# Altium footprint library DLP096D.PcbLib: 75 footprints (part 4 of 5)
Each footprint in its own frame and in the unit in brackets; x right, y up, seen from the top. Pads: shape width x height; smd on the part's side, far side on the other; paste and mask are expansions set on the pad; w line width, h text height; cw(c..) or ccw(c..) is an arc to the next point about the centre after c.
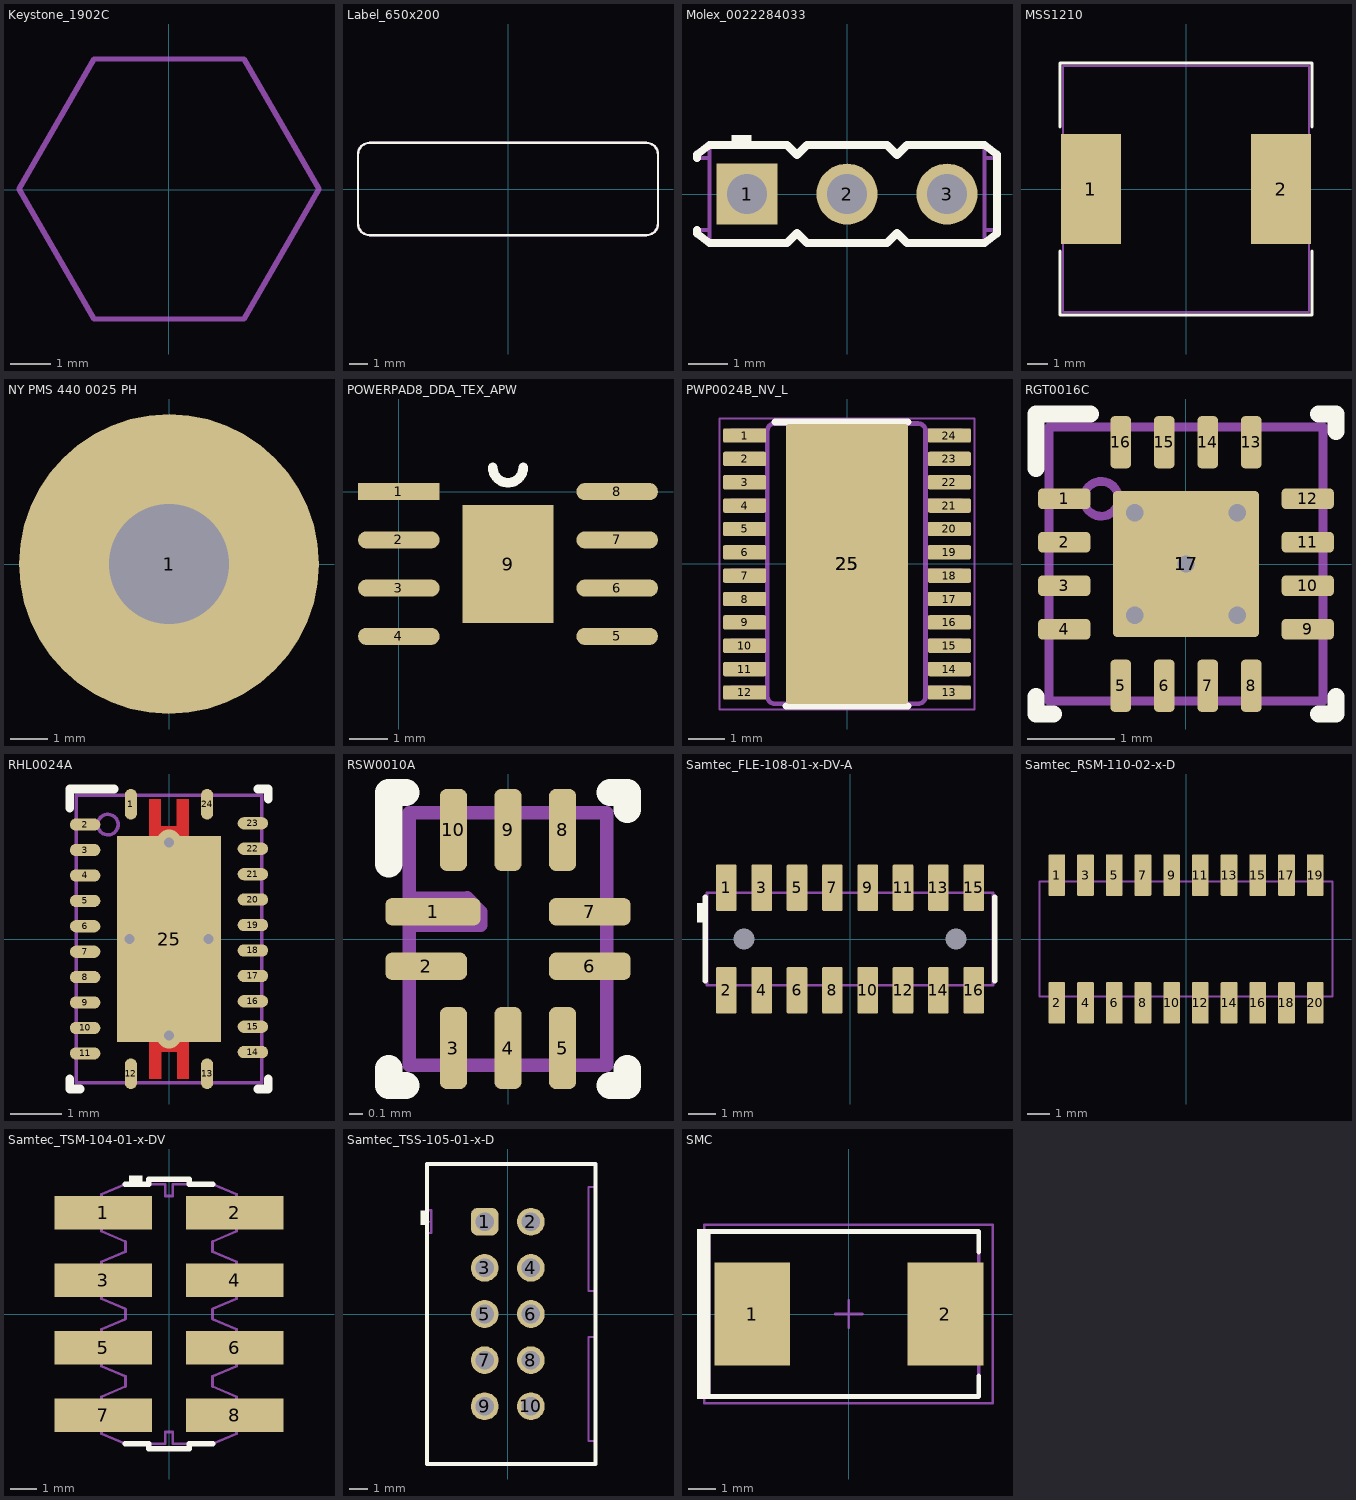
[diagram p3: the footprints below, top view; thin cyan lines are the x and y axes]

## Keystone_1902C [mil] "Hex Standoff, 4-40 threaded, nylon"
height 500
pads (1):
  round 1 on Mech3: 0(0,0)
Mechanical 5:
  lines w5: -145.29,0.49 -72.56,-125.49 72.92,-125.49 145.65,0.49 72.92,126.47 -72.56,126.47 -145.29,0.49
  text ".Designator" at -60,-20 h40
3D body "Keystone_1902C.stp": height 501, standoff 1, extent -144.95,-125.98 146,125.98

## Label_650x200 [mil] "Thermal Transfer Label"
height 1
pads (1):
  round 1 on Mech13: 0(0,0)
Top Overlay:
  lines w5: -325,-75 ccw(c-300,-75) -300,-100 300,-100 ccw(c300,-75) 325,-75 325,75 ccw(c300,75) 300,100 -300,100 ccw(c-300,75) -325,75 -325,-75
Mechanical 5:
  lines w5: -325,-75 ccw(c-300,-75) -300,-100 300,-100 ccw(c300,-75) 325,-75 325,75 ccw(c300,75) 300,100 -300,100 ccw(c-300,75) -325,75 -325,-75
  text ".Designator" at -60,-20 h40
3D body: height 1, standoff 0, extent -325.02,-100.02 325.02,100.02

## Molex_0022284033 [mm] "Header, 2.54mm, 3x1, TH"
height 8.88
pads (3):
  rect 1.55x1.55 hole 1.02: 1(-2.54,0)
  round 1.55 hole 1.02: 2(0,0) 3(2.54,0)
Top Overlay:
  rectangle: -2.93,1.245 -2.43,1.5
  lines w0.2: -3.81,-0.914 -3.81,-1.003 -3.492,-1.245 -1.524,-1.245 -1.27,-0.991 -1.016,-1.245 1.016,-1.245 1.27,-0.991 1.524,-1.245 3.492,-1.245 3.81,-1.003 3.81,-0.914 3.81,0.914 3.81,1.003 3.492,1.245 1.524,1.245 1.27,0.991 1.016,1.245 -1.016,1.245 -1.27,0.991 -1.524,1.245 -3.492,1.245 -3.81,1.003 -3.81,0.914
Mechanical 5:
  lines w0.1: -3.492,-1.168 -3.492,1.168 ; -3.492,-0.914 -3.81,-0.914 -3.81,-1.003 -3.492,-1.245 -1.524,-1.245 -1.27,-0.991 -1.016,-1.245 1.016,-1.245 1.27,-0.991 1.524,-1.245 3.492,-1.245 3.81,-1.003 3.81,-0.914 ; -3.492,0.914 -3.81,0.914 -3.81,1.003 -3.492,1.245 -1.524,1.245 -1.27,0.991 -1.016,1.245 1.016,1.245 1.27,0.991 1.524,1.245 3.492,1.245 3.81,1.003 3.81,0.914 ; 3.492,-1.168 3.492,1.168 ; 3.492,-0.914 3.81,-0.914 ; 3.492,0.914 3.81,0.914 ; 3.81,-0.914 3.81,0.914
  text ".Designator" at -2,-0.7 h1.85
3D body "022284033.stp": height 8.4, standoff -3.16, extent -3.81,-1.244 3.81,1.245

## MSS1210 [mm] "Coilcraft MSS1210 series"
height 10.2
pads (2):
  rect 3x5.5 smd: 1(-4.75,0) 2(4.75,0)
Top Overlay:
  lines w0.17: -6.3,-3.1 -6.3,-6.3 6.3,-6.3 6.3,-3.1 ; -6.3,3.1 -6.3,6.3 6.3,6.3 6.3,3.1
Mechanical 5:
  lines w0.1: -6.15,-6.15 6.15,-6.15 6.15,6.15 -6.15,6.15 -6.15,-6.15
  text ".Designator" at -2,-0.5 h1.02
3D body: height 10.2, standoff 0, extent -6.149,-6.149 6.149,6.149

## NY PMS 440 0025 PH [mm] "4-40 nylon screw and mounting hole"
height 1.905
pads (1):
  round 8 hole 3.2: 1(0,0)
Mechanical 5:
  circle w0.127: c0,0 r3.789
  text ".Designator" at -1.524,-0.508 h1.02
3D body "B_F_NY PMS 440 0025 PH.stp": height 2.69, standoff -8.74, extent -3.302,-3.3 3.296,3.3

## PCBComponent_1 [mm]

## POWERPAD8_DDA_TEX_APW [mm]
pads (9):
  rect 2.15x0.45 smd: 1(0,0)
  oval 2.15x0.45 smd: 2(0,-1.27) 3(0,-2.54) 4(0,-3.81) 5(5.75,-3.81) 6(5.75,-2.54) 7(5.75,-1.27) 8(5.75,0)
  rect 2.4x3.1 smd: 9(2.875,-1.905)
Top Overlay:
  lines w0.254: 2.475,0.635 ccw(c2.875,0.635) 3.275,0.635

## PWP0024B_NV_L [mm] "TSOP, 24-Leads, Body 7.9x4.5mm (max), Pitch 0.65mm, IPC High Density"
height 1.2
pads (27):
  rrect25% 1.2x0.4 smd: 1(-2.85,3.575) 2(-2.85,2.925) 3(-2.85,2.275) 4(-2.85,1.625) 5(-2.85,0.975) 6(-2.85,0.325) 7(-2.85,-0.325) 8(-2.85,-0.975) 9(-2.85,-1.625) 10(-2.85,-2.275) 11(-2.85,-2.925) 12(-2.85,-3.575) 13(2.85,-3.575) 14(2.85,-2.925) 15(2.85,-2.275) 16(2.85,-1.625) 17(2.85,-0.975) 18(2.85,-0.325) 19(2.85,0.325) 20(2.85,0.975) 21(2.85,1.625) 22(2.85,2.275) 23(2.85,2.925) 24(2.85,3.575)
  rrect6% 3.4x7.8 smd paste-2 mask-2: 25(0,0)
  rrect50% 2.4x5.16 on Top Paste: 25(0,0)
  rrect50% 2.4x5.16 on Top Solder: 25(0,0)
Top Overlay:
  lines w0.2: -2,3.95 1.7,3.95 ; -1.7,-3.95 1.7,-3.95
Mechanical 5:
  drawing of 298 lines, arcs and shapes, not listed
  text ".Designator" at -1.854,-0.508 h1.02
Mechanical 15:
  lines w0.05: -3.55,-4.05 3.55,-4.05 3.55,4.05 -3.55,4.05 -3.55,-4.05
  lines w0.1: -0.5,0 0.5,0 ; 0,-0.5 0,0.5
3D body "PWP0024B.stp": height 1.2, standoff 0, extent -3.208,-3.9 3.208,3.9

## RGT0016C [mm] "QFN, 16-Leads, Body 3x3mm, Pitch 0.5mm, Thermal Pad 1.7x1.7mm, TI Recommended"
height 1
pads (18):
  rrect42% 0.6x0.24 smd: 1(-1.4,0.75) 2(-1.4,0.25) 3(-1.4,-0.25) 4(-1.4,-0.75) 9(1.4,-0.75) 10(1.4,-0.25) 11(1.4,0.25) 12(1.4,0.75)
  rrect42% 0.24x0.6 smd: 5(-0.75,-1.4) 6(-0.25,-1.4) 7(0.25,-1.4) 8(0.75,-1.4) 13(0.75,1.4) 14(0.25,1.4) 15(-0.25,1.4) 16(-0.75,1.4)
  rrect50% 1.55x1.55 on Top Paste: 17(0,0)
  rrect6% 1.68x1.68 smd paste-0.85: 17(0,0)
via 0,0 diameter 0.5 hole 0.2
via -0.59,0.59 diameter 0.5 hole 0.2
via -0.59,-0.59 diameter 0.5 hole 0.2
via 0.59,-0.59 diameter 0.5 hole 0.2
via 0.59,0.59 diameter 0.5 hole 0.2
Top Overlay:
  lines w0.2: -1.725,-1.525 -1.725,-1.725 -1.525,-1.725 ; -1.725,1.1 -1.725,1.725 -1.1,1.725 ; 1.525,-1.725 1.725,-1.725 1.725,-1.525 ; 1.525,1.725 1.725,1.725 1.725,1.525
Mechanical 5:
  circle w0.1: c-0.975,0.75 r0.2
  lines w0.1: -1.575,-1.575 -1.575,1.575 1.575,1.575 1.575,-1.575 -1.575,-1.575
  text ".Designator" at -1.425,-0.55 h1.4
3D body "RGT0016C.stp": height 1, standoff 0, extent -1.5,-1.5 1.5,1.5

## RHL0024A [mm]
height 1
pads (25):
  oval 0.24x0.6 smd: 1(-0.75,2.65) 12(-0.75,-2.65) 13(0.75,-2.65) 24(0.75,2.65)
  oval 0.6x0.24 smd: 2(-1.65,2.25) 3(-1.65,1.75) 4(-1.65,1.25) 5(-1.65,0.75) 6(-1.65,0.25) 7(-1.65,-0.25) 8(-1.65,-0.75) 9(-1.65,-1.25) 10(-1.65,-1.75) 11(-1.65,-2.25) 14(1.65,-2.225) 15(1.65,-1.725) 16(1.65,-1.225) 17(1.65,-0.725) 18(1.65,-0.225) 19(1.65,0.275) 20(1.65,0.775) 21(1.65,1.275) 22(1.65,1.775) 23(1.65,2.275)
  rect 2.05x4.05 smd paste-1.1: 25(0,0)
via 0,-1.9 diameter 0.5 hole 0.2
via 0,1.9 diameter 0.5 hole 0.2
via 0.775,0 diameter 0.5 hole 0.2
via -0.775,0 diameter 0.5 hole 0.2
Top Layer:
  region: 0.396,-2 0.154,-2 0.154,-2.75 0.396,-2.75
  region: -0.152,-2 -0.394,-2 -0.394,-2.75 -0.152,-2.75
  rectangle: -0.395,2.024 0.395,2.225
  rectangle: 0.152,2 0.394,2.75
  rectangle: -0.396,2 -0.154,2.75
  rectangle: -0.395,-2.225 0.395,-2.024
Top Overlay:
  lines w0.17: -1.95,-2.75 -1.95,-2.95 -1.75,-2.95 ; -1.95,2.575 -1.95,2.95 -1.075,2.95 ; 1.75,-2.95 1.95,-2.95 1.95,-2.75 ; 1.75,2.95 1.95,2.95 1.95,2.75
Top Paste:
  rectangle: -0.895,0.1 0.894,1.798
  rectangle: -0.895,-1.798 0.894,-0.1
Mechanical 5:
  circle w0.07: c-1.202,2.25 r0.202
  lines w0.07: -1.825,-2.825 1.825,-2.825 1.825,2.825 -1.825,2.825 -1.825,-2.825
  text ".Designator" at -1.65,-0.475 h0.9
3D body: height 1, standoff 0, extent -1.824,-2.824 1.824,2.824
3D body: height 1.01, standoff 0.9, extent -1.403,2.049 -1.001,2.451

## RSW0010A [mm] "QFN, 10-Leads, Body 1.8x1.4 mm, Pitch 0.4mm, TI Recommended"
height 0.55
pads (10):
  rrect50% 0.7x0.2 smd: 1(-0.55,0.2)
  rrect50% 0.6x0.2 smd: 2(-0.6,-0.2) 6(0.6,-0.2) 7(0.6,0.2)
  rrect50% 0.2x0.6 smd: 3(-0.4,-0.8) 4(0,-0.8) 5(0.4,-0.8) 8(0.4,0.8) 9(0,0.8) 10(-0.4,0.8)
Top Overlay:
  lines w0.2: -0.875,-0.95 -0.875,-1.075 -0.75,-1.075 ; -0.875,0.55 -0.875,1.075 -0.75,1.075 ; 0.75,-1.075 0.875,-1.075 0.875,-0.95 ; 0.75,1.075 0.875,1.075 0.875,0.95
Mechanical 5:
  lines w0.1: -0.725,0.1 -0.2,0.1 -0.2,0.2 -0.3,0.3 -0.725,0.3 ; -0.725,-0.925 0.725,-0.925 0.725,0.925 -0.725,0.925 -0.725,-0.925
  text ".Designator" at 0.125,0.725 h0.38
3D body "RSW0010A.stp": height 0.56, standoff 0.01, extent -0.7,-0.9 0.7,0.9

## Samtec_FLE-108-01-x-DV-A [mm] "Receptacle, 1.27mm, 8x2, SMT"
height 4.68
pads (18):
  rrect14% 0.74x1.675 smd: 1(-4.445,1.843) 2(-4.445,-1.842) 3(-3.175,1.843) 4(-3.175,-1.842) 5(-1.905,1.843) 6(-1.905,-1.842) 7(-0.635,1.843) 8(-0.635,-1.842) 9(0.635,1.843) 10(0.635,-1.842) 11(1.905,1.843) 12(1.905,-1.842) 13(3.175,1.843) 14(3.175,-1.842) 15(4.445,1.843) 16(4.445,-1.842)
  round 0.46 hole 0.76 unplated: ""(-3.81,0) ""(3.81,0)
Top Overlay:
  rectangle: -5.5,0.6 -5.2,1.3
  lines w0.2: -5.2,-1.5 -5.2,1.5 ; 5.2,-1.5 5.2,1.5
Mechanical 5:
  lines w0.1: -4.699,-1.664 -4.699,-2.297 -4.191,-2.297 -4.191,-1.664 ; -4.699,1.664 -4.699,2.297 -4.191,2.297 -4.191,1.664 ; -3.429,-1.664 -3.429,-2.297 -2.921,-2.297 -2.921,-1.664 ; -3.429,1.664 -3.429,2.297 -2.921,2.297 -2.921,1.664 ; -2.159,-1.664 -2.159,-2.297 -1.651,-2.297 -1.651,-1.664 ; -2.159,1.664 -2.159,2.297 -1.651,2.297 -1.651,1.664 ; -0.889,-1.664 -0.889,-2.297 -0.381,-2.297 -0.381,-1.664 ; -0.889,1.664 -0.889,2.297 -0.381,2.297 -0.381,1.664 ; 0.381,-1.664 0.381,-2.297 0.889,-2.297 0.889,-1.664 ; 0.381,1.664 0.381,2.297 0.889,2.297 0.889,1.664 ; 1.651,-1.664 1.651,-2.297 2.159,-2.297 2.159,-1.664 ; 1.651,1.664 1.651,2.297 2.159,2.297 2.159,1.664 ; 2.921,-1.664 2.921,-2.297 3.429,-2.297 3.429,-1.664 ; 2.921,1.664 2.921,2.297 3.429,2.297 3.429,1.664 ; 4.191,-1.664 4.191,-2.297 4.699,-2.297 4.699,-1.664 ; 4.191,1.664 4.191,2.297 4.699,2.297 4.699,1.664 ; -5.137,-1.664 5.137,-1.664 5.137,1.664 -5.137,1.664 -5.137,-1.664
  text ".Designator" at -2.6,-0.4 h1.52
3D body "FLE-108-01-G-DV-A.stp": height 4.55, standoff -0.58, extent -5.137,-2.297 5.137,2.298

## Samtec_RSM-110-02-x-D [mm] "Receptacle, 1.27mm, 10x2, SMT"
height 6.354
pads (20):
  rrect14% 0.74x1.84 smd: 1(-5.715,2.825) 2(-5.715,-2.825) 3(-4.445,2.825) 4(-4.445,-2.825) 5(-3.175,2.825) 6(-3.175,-2.825) 7(-1.905,2.825) 8(-1.905,-2.825) 9(-0.635,2.825) 10(-0.635,-2.825) 11(0.635,2.825) 12(0.635,-2.825) 13(1.905,2.825) 14(1.905,-2.825) 15(3.175,2.825) 16(3.175,-2.825) 17(4.445,2.825) 18(4.445,-2.825) 19(5.715,2.825) 20(5.715,-2.825)
Mechanical 5:
  lines w0.1: -5.918,-2.54 -5.918,-3.238 -5.512,-3.238 -5.512,-2.54 ; -5.918,2.54 -5.918,3.238 -5.512,3.238 -5.512,2.54 ; -4.648,-2.54 -4.648,-3.238 -4.242,-3.238 -4.242,-2.54 ; -4.648,2.54 -4.648,3.238 -4.242,3.238 -4.242,2.54 ; -3.378,-2.54 -3.378,-3.238 -2.972,-3.238 -2.972,-2.54 ; -3.378,2.54 -3.378,3.238 -2.972,3.238 -2.972,2.54 ; -2.108,-2.54 -2.108,-3.238 -1.702,-3.238 -1.702,-2.54 ; -2.108,2.54 -2.108,3.238 -1.702,3.238 -1.702,2.54 ; -0.838,-2.54 -0.838,-3.238 -0.432,-3.238 -0.432,-2.54 ; -0.838,2.54 -0.838,3.238 -0.432,3.238 -0.432,2.54 ; 0.432,-2.54 0.432,-3.238 0.838,-3.238 0.838,-2.54 ; 0.432,2.54 0.432,3.238 0.838,3.238 0.838,2.54 ; 1.702,-2.54 1.702,-3.238 2.108,-3.238 2.108,-2.54 ; 1.702,2.54 1.702,3.238 2.108,3.238 2.108,2.54 ; 2.972,-2.54 2.972,-3.238 3.378,-3.238 3.378,-2.54 ; 2.972,2.54 2.972,3.238 3.378,3.238 3.378,2.54 ; 4.242,-2.54 4.242,-3.238 4.648,-3.238 4.648,-2.54 ; 4.242,2.54 4.242,3.238 4.648,3.238 4.648,2.54 ; 5.512,-2.54 5.512,-3.238 5.918,-3.238 5.918,-2.54 ; 5.512,2.54 5.512,3.238 5.918,3.238 5.918,2.54 ; -6.477,-2.54 -6.477,2.54 6.477,2.54 6.477,-2.54 -6.477,-2.54
  text ".Designator" at -2.5,-0.5 h1.52
3D body "RSM-110-02-L-D.stp": height 6.1, standoff 0, extent -6.477,-3.238 6.477,3.239

## Samtec_TSM-104-01-x-DV [mm] "Header, 2.54mm, 4x2, SMT"
height 10.16
pads (8):
  rect 3.68x1.27 smd: 1(-2.475,3.81) 2(2.475,3.81) 3(-2.475,1.27) 4(2.475,1.27) 5(-2.475,-1.27) 6(2.475,-1.27) 7(-2.475,-3.81) 8(2.475,-3.81)
Top Overlay:
  rectangle: -1.5,4.89 -1,5.22
  lines w0.2: -1.651,-4.89 -0.762,-4.89 -0.762,-5.08 0.762,-5.08 0.762,-4.89 1.651,-4.89 ; -1.651,4.89 -0.762,4.89 -0.762,5.08 0.762,5.08 0.762,4.89 1.651,4.89
Mechanical 5:
  lines w0.1: -2.54,-4.128 -3.848,-4.128 -3.848,-3.493 -2.54,-3.493 ; -2.54,-1.587 -3.848,-1.587 -3.848,-0.953 -2.54,-0.953 ; -2.54,0.953 -3.848,0.953 -3.848,1.587 -2.54,1.587 ; -2.54,3.493 -3.848,3.493 -3.848,4.128 -2.54,4.128 ; -1.651,-2.731 -2.54,-3.112 -2.54,-4.509 -1.651,-4.89 -0.146,-4.89 -0.146,-4.445 0.146,-4.445 0.146,-4.89 1.651,-4.89 2.54,-4.509 2.54,-3.112 1.651,-2.731 ; -1.651,-2.349 -2.54,-1.968 -2.54,-0.572 -1.651,-0.191 ; -1.651,0.191 -2.54,0.572 -2.54,1.968 -1.651,2.35 ; -1.651,2.731 -2.54,3.112 -2.54,4.509 -1.651,4.89 -0.146,4.89 -0.146,4.445 0.146,4.445 0.146,4.89 1.651,4.89 2.54,4.509 2.54,3.112 1.651,2.731 ; -1.638,-2.731 -1.638,-2.349 ; -1.638,-0.191 -1.638,0.191 ; -1.638,2.35 -1.638,2.731 ; -0.762,-4.89 -0.762,-5.08 0.762,-5.08 0.762,-4.89 ; -0.762,4.89 -0.762,5.08 0.762,5.08 0.762,4.89 ; 1.638,-2.731 1.638,-2.349 ; 1.638,-0.191 1.638,0.191 ; 1.638,2.35 1.638,2.731 ; 1.651,-2.349 2.54,-1.968 2.54,-0.572 1.651,-0.191 ; 1.651,0.191 2.54,0.572 2.54,1.968 1.651,2.35 ; 2.54,-4.128 3.848,-4.128 3.848,-3.493 2.54,-3.493 ; 2.54,-1.587 3.848,-1.587 3.848,-0.953 2.54,-0.953 ; 2.54,0.953 3.848,0.953 3.848,1.587 2.54,1.587 ; 2.54,3.493 3.848,3.493 3.848,4.128 2.54,4.128
  text ".Designator" at -2.1,0.8 h1.02
3D body "TSM-104-01-L-DV.stp": height 9.65, standoff 0, extent -3.848,-5.08 3.848,5.08

## Samtec_TSS-105-01-x-D [mm] "Header(shrouded), 2.54mm, 5x2, TH"
height 9.53
pads (10):
  rrect50% 1.53x1.53 hole 1.02: 1(-1.27,5.08)
  round 1.53 hole 1.02: 2(1.27,5.08) 3(-1.27,2.54) 4(1.27,2.54) 5(-1.27,0) 6(1.27,0) 7(-1.27,-2.54) 8(1.27,-2.54) 9(-1.27,-5.08) 10(1.27,-5.08)
Top Overlay:
  rectangle: -4.8,4.9 -4.4,5.7
  lines w0.2: -4.445,-8.255 4.826,-8.255 4.826,8.255 -4.445,8.255 -4.445,-8.255
Mechanical 5:
  lines w0.1: -4.216,5.08 -4.445,5.08 ; -4.445,4.445 -4.191,4.445 ; -4.445,4.445 -4.445,2.54 -4.445,-2.54 -4.445,-8.255 4.826,-8.255 4.826,-6.985 4.445,-6.985 4.445,-1.27 4.826,-1.27 4.826,1.27 4.445,1.27 4.445,6.985 4.826,6.985 4.826,8.255 -4.445,8.255 -4.445,5.715 ; -4.445,4.445 -4.445,4.47 ; -4.445,4.445 -4.191,4.445 ; -4.445,4.47 -4.216,4.47 -4.216,5.69 -4.445,5.69 ; -4.445,4.47 -4.445,5.08 ; -4.445,5.08 -4.445,5.69 ; -4.445,5.69 -4.445,5.715 ; -4.445,5.715 -4.191,5.715 ; -4.445,5.715 -4.191,5.715 ; -4.191,4.445 -4.191,5.715 ; -4.191,4.445 -4.191,5.715
  text ".Designator" at -2.6,-0.6 h1.52
3D body "TSS-105-01-T-D.stp": height 9.09, standoff -3.1, extent -4.454,-8.255 4.817,8.255

## SMC [mil] "Molded Diode, 2-Leads, Body 6.9x5.8mm, IPC Medium Density, based on OnSemi component dimensions and land patterns"
height 94.88
pads (2):
  rect 110x150 smd: 1(-140.49,0) 2(140.49,0)
Top Overlay:
  rectangle: -221,-123.5 -201,123.5
  lines w7: -210,-120 189,-120 189,-90.25 ; -210,120 189,120 189,90.25
Mechanical 5:
  rectangle: -221,-123.5 -201,123.5
  lines w5: -210,-120 189,-120 189,120 -210,120
  text ".Designator" at -85,-20 h40
Mechanical 15:
  lines w3.94: -19.69,0 19.68,0 ; 0,-19.68 0,19.68 ; -210.46,-129.92 -210.46,129.92 209.38,129.92 209.38,-129.92 -210.46,-129.92
3D body "SMC_nominal.stp": height 91.35, standoff 0.6, extent -156.49,-116.13 156.5,116.15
